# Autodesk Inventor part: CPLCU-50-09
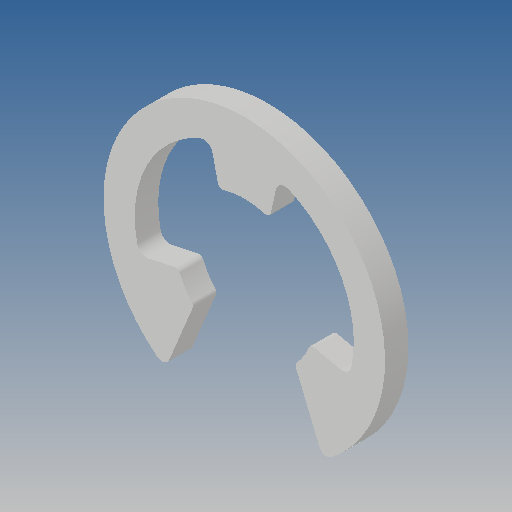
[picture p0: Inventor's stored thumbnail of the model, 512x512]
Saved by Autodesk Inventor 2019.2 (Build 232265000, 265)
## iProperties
Created: 2010-03
Part Number: CPLCU-50-09
Material: Ogólny
Document SubType Name: Modeling
Designer: CADENGINEERING4
Density: 1 g/cm^3
Appearance: Domyślna
Author: CADENGINEERING4
Revision Number: 3LAST_VERSION
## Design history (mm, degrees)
feature "Baza1"
node "Bryła1"
